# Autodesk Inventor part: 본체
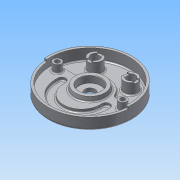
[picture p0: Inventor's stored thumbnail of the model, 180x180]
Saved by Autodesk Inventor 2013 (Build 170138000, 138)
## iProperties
Created: 2015-04
Part Number: 본체
Material: 알루미늄 6061
Document SubType Name: Modeling
Designer: Administrator
Density: 2.71 g/cm^3
Mass: 1053.1 g
Surface Area: 1027.64 cm^2
Volume: 388.598 cm^3
Author: Administrator
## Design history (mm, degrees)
sketch "스케치1"
  geometry: C1 r 95 at (0, 0); 1 further point
  constraints: 1 centre point, 1 coincident
  dimensions: "d5" = 190 diameter of C1
extrude "돌출1" new body sketch "스케치1" distance "d7" = 32; taper "d8" = 0 deg
hole "구멍1" diameter "d11" = 180; stored, may be unused: countersink angle "d15" = 90 deg, drill point angle "d17" = 0 deg; dims "d9" = 10, "d10" = 10, "d12" = 6, "d13" = 4, "d14" = 2, "d16" = 18
sketch "스케치6"
  geometry: C1 r 9 at (-74, 0); C2 r 9 at (74, 0); A1 r 90 centre (0, 0) between (90, 0) and (90, 0) reference; A2 r 74 centre (0, 0) between (-74, 0) and (74, 0)
  constraints: 3 centre point, 2 point on circle, 1 coincident
  dimensions: "d56" = 148 diameter of A2; "d57" = 18 diameter of C1; "d58" = 18 diameter of C2
extrude "돌출5" join sketch "스케치6" distance "d59" = 18; taper "d60" = 0 deg
sketch "스케치8"
  geometry: L1 (-76.916, 12)-(-47.117, 12); L2 (47.117, 12)-(76.916, 12); C1 r 90 at (0, 0) reference; A1 r 42 centre (0, 0) between (38.056, 17.769) and (-38.056, 17.769); A2 r 90 centre (0, 0) between (86.53, 24.75) and (-86.53, 24.75); A3 r 10 centre (-76.916, 22) between (-86.53, 24.75) and (-76.916, 12); A4 r 10 centre (-47.117, 22) between (-47.117, 12) and (-38.056, 17.769); A5 r 10 centre (47.117, 22) between (38.056, 17.769) and (47.117, 12); A6 r 10 centre (76.916, 22) between (76.916, 12) and (86.53, 24.75); 4 further points
  constraints: 16 point on circle, 8 tangent, 6 centre point, 4 end point, 4 equal radius, 4 point on line, 2 coincident, 2 horizontal
  dimensions: "d86" = 84 diameter of A1; "d87" = 12 distance from line of C1.centre L1; "d88" = 12 distance from line of L2 C1.centre; "d89" = 10 radius of A3
extrude "돌출7" cut sketch "스케치8" distance "d90" = 7; taper "d91" = 0 deg
sketch "스케치9"
  geometry: L1 (42, 14)-(17.769, 14) reference; L2 (24.75, 14)-(-90, 14) reference; L3 (0, 0)-(0, 24); L4 (0, 24)-(33.237, 24); L5 (33.237, 24)-(35, 14); L6 (35, 14)-(0, 14)
  constraints: 8 end point, 3 point on line, 2 perpendicular
  dimensions: "d92" = 100 deg angle of L1 L5; "d93" = 70 diameter of L5.end L3; "d95" = 10 distance between parallel lines of L1 L4
revolve "회전2" sketch "스케치9" stored, may be unused: angle "d96" = 90 deg
hole "구멍5" diameter "d99" = 23; stored, may be unused: countersink angle "d103" = 90 deg, drill point angle "d105" = 0 deg; dims "d97" = 10, "d98" = 10, "d100" = 6, "d101" = 50, "d102" = 15, "d104" = 18
sketch "스케치10"
  geometry: L1 (76.916, 12)-(47.117, 12) reference; L2 (-106.837, 52)-(100.665, 52); C1 r 15 at (-40, 52); C2 r 15 at (40, 52); A1 r 42 centre (0, 0) between (38.056, 17.769) and (-38.056, 17.769) reference; A2 r 40 centre (0, 52) between (-40, 52) and (40, 52)
  constraints: 3 centre point, 3 point on line, 2 end point, 2 point on circle, 1 parallel
  dimensions: "d106" = 52 distance from line of A1.centre L2; "d107" = 80 diameter of A2; "d108" = 30 diameter of C1; "d109" = 30 diameter of C2
extrude "돌출8" join sketch "스케치10" distance "d110" = 25; taper "d111" = 0 deg
hole "구멍6" diameter "d120" = 20; stored, may be unused: countersink angle "d124" = 90 deg, drill point angle "d126" = 0 deg; dims "d118" = 10, "d119" = 10, "d121" = 6, "d122" = 50, "d123" = 15, "d125" = 18
hole "구멍7" diameter "d129" = 20; stored, may be unused: countersink angle "d133" = 90 deg, drill point angle "d135" = 0 deg; dims "d127" = 10, "d128" = 10, "d130" = 6, "d131" = 50, "d132" = 15, "d134" = 18
sketch "스케치13"
  geometry: L1 (0, 0)-(0, -74) reference; L2 (36.062, -36.062)-(52.326, -52.326); L3 (-36.062, -36.062)-(-52.326, -52.326); C1 r 95 at (0, 0) reference; A1 r 51 centre (0, 0) between (-36.062, -36.062) and (36.062, -36.062); A2 r 74 centre (0, 0) between (-52.326, -52.326) and (52.326, -52.326)
  constraints: 6 end point, 5 point on circle, 2 centre point, 2 coincident, 1 vertical
  dimensions: "d138" = 102 diameter of A1 (derived)
extrude "돌출9" join sketch "스케치13" distance "d142" = 5.5; taper "d143" = 0 deg
fillet "모깎기1" dims "d144" = 5
fillet "모깎기2" dims "d145" = 5
fillet "모깎기3" dims "d146" = 5
fillet "모깎기5" dims "d159" = 0.3
fillet "모깎기6" dims "d204" = 5
chamfer "모따기1" distance "d161" = 1; stored, may be unused: second distance "d162" = 2, angle "d163" = 45 deg
chamfer "모따기2" distance "d164" = 1; stored, may be unused: second distance "d165" = 2, angle "d166" = 45 deg
fillet "모깎기7" dims "d167" = 3
sketch "스케치16"
  geometry: L1 (0, 0)-(-95, 0); L2 (0, 0)-(95, 0); L3 (-85.36, -7.468)-(-94.638, -8.28); L4 (85.36, -7.468)-(94.638, -8.28); A1 r 95 centre (0, 0) between (94.638, -8.28) and (-94.638, -8.28) reference; A2 r 95 centre (0, 0) between (-94.638, -8.28) and (94.638, -8.28); A3 r 85.686 centre (0, 0) between (-85.36, -7.468) and (85.36, -7.468)
  constraints: 8 end point, 6 point on circle, 2 centre point, 2 coincident, 1 collinear, 1 concentric, 1 horizontal
  dimensions: "d168" = 5 deg angle of L4 L2; "d169" = 5 deg angle of L3 L1
extrude "돌출12" cut sketch "스케치16" distance "d170" = 5; taper "d171" = 0 deg
sketch "스케치17"
  geometry: C1 r 9 at (-74, 0) reference; C2 r 9 at (74, 0) reference; 2 further points
  constraints: 2 coincident
hole "구멍8" sketch "스케치17" at (-74, 0), (74, 0) diameter "d172" = 11; stored, may be unused: countersink angle "d176" = 90 deg, drill point angle "d178" = 0 deg; dims "d173" = 6, "d174" = 18, "d175" = 11, "d177" = 18
sketch "스케치18"
  geometry: L1 (0, -56)-(0, -69); C1 r 68 at (0, 0); A1 r 69 centre (0, 0) between (-45.127, -52.198) and (45.127, -52.198) reference; A2 r 56 centre (0, 0) between (-35.904, -42.975) and (35.904, -42.975) reference; 1 further point
  constraints: 2 end point, 2 point on circle, 1 centre point, 1 coincident, 1 midpoint, 1 other
  dimensions: "d179" = 136 diameter of C1
feature "엠보싱1" sketch "스케치18" dims "d86" = 84, "d87" = 12, "d88" = 12, "d89" = 10, "d180" = 0.5, "d181" = 0
sketch "스케치19"
  geometry: L1 (-6, 20.634)-(6, 20.634); L2 (6, 20.634)-(6, -19.694); L3 (6, -19.694)-(-6, -19.694); L4 (-6, -19.694)-(-6, 20.634); L5 (56.541, 6)-(100.942, 6); L6 (100.942, 6)-(100.942, -6); L7 (100.942, -6)-(56.541, -6); L8 (56.541, -6)-(56.541, 6); C1 r 10 at (0, 0) reference; C2 r 15 at (80, 0) reference; C3 r 10 at (80, 0) reference; 1 further point
  constraints: 16 end point, 4 parallel, 2 horizontal, 2 perpendicular
  dimensions: "d182" = 6 distance from line of L2 C1.centre; "d183" = 12 distance between parallel lines of L4 L2; "d186" = 6 distance from line of L5 C2.centre; "d187" = 12 distance between parallel lines of L7 L5
extrude "돌출13" cut sketch "스케치19" distance "d188" = 3; taper "d189" = 0 deg
sketch "스케치20"
  geometry: L1 (-47.117, 12)-(-74, 12) reference; L2 (-74, 12)-(-76.916, 12) reference; L3 (-104.875, -19)-(111.353, -19); L4 (-104.875, -14)-(111.353, -14); L5 (-41, -14)-(-41, -19); L6 (41, -14)-(41, -19); L7 (59, -14)-(59, -19) reference; L8 (-50, -8.649)-(-50, -28.3); L9 (50, -13.23)-(50, -23.111); L10 (-59, -14)-(-59, -19); A1 r 42 centre (0, 0) between (38.056, 17.769) and (-38.056, 17.769) reference; A2 r 37.517 centre (0, 0) between (-37.446, -2.304) and (37.446, -2.304) reference; A3 r 9 centre (50, -14) between (59, -14) and (41, -14); A4 r 9 centre (-50, -14) between (-41, -14) and (-59, -14); A5 r 59 centre (0, -19) between (-59, -19) and (59, -19); A6 r 59 centre (0, -19) between (58.788, -14) and (-50.2, 12); A7 r 41 centre (0, -19) between (-41, -19) and (41, -19); A8 r 41 centre (0, -19) between (37.446, -2.304) and (-37.446, -2.304)
  constraints: 16 end point, 14 point on circle, 11 point on line, 7 parallel, 6 centre point, 2 vertical, 1 coincident, 1 perpendicular
  dimensions: "d190" = 19 distance from line of L3 A1.centre; "d191" = 5 distance between parallel lines of L4 L3; "d195" = 18 diameter of A3; "d196" = 18 diameter of A4; "d198" = 9 distance between parallel lines of L6 L9
extrude "돌출14" cut sketch "스케치20" distance "d200" = 7; taper "d201" = 0 deg
fillet "모깎기8" dims "d202" = 3
fillet "모깎기9" dims "d203" = 3
node "솔리드1"
other parameters: "d30" = 118, "d31" = 82, "d85" = 12, "d136" = 148, "d140" = 45 deg, "d141" = 90 deg, "d192" = 118, "d194" = 82, "d197" = 9
